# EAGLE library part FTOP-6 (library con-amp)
AMP connector
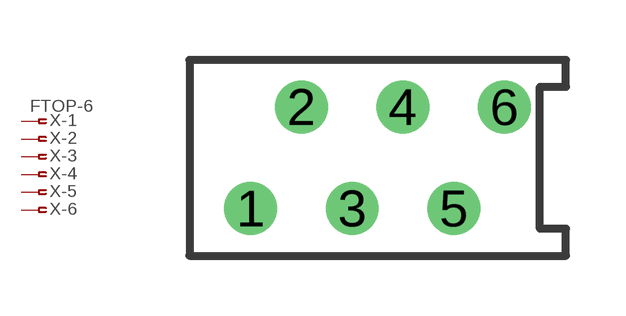
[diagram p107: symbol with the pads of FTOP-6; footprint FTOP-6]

Designator prefix X; gates -1=PIN-FV -2=PIN-F -3=PIN-F -4=PIN-F -5=PIN-F -6=PIN-F

## FTOP-6 (OC_FARNELL: unknown; OC_NEWARK: unknown)  [FTOP-6]
1  -1:1  pas
2  -2:1  pas
3  -3:1  pas
4  -4:1  pas
5  -5:1  pas
6  -6:1  pas

## Footprint FTOP-6 (pad centres in mm)
AMP connector
drill 0.813 round: 1 -3.175,-1.27; 2 -1.905,1.27; 3 -0.635,-1.27; 4 0.635,1.27; 5 1.905,-1.27; 6 3.175,1.27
